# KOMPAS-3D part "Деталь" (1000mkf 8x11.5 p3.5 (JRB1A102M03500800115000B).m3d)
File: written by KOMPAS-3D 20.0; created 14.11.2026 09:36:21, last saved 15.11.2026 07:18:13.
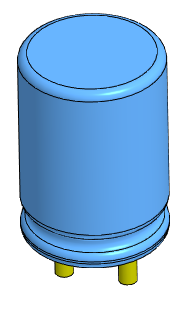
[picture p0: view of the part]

Document properties: Полное имя файла: D:\myProjects\Progect_esp32\box_compas\прочее\1000mkf 8x11.5 p3.5.m3d

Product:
- Part/product: Деталь
    Масса: 0.00447634

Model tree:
1. Эскиз:1
2. Элемент вращения:1
     Угол 1 = 360
3. Скругление:1  (with: Элемент вращения:1)
     Радиус = 0.5
4. Эскиз:2  (with: Элемент вращения:1, Скругление:1)
5. Элемент выдавливания:1
     Расстояние 1 = 3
